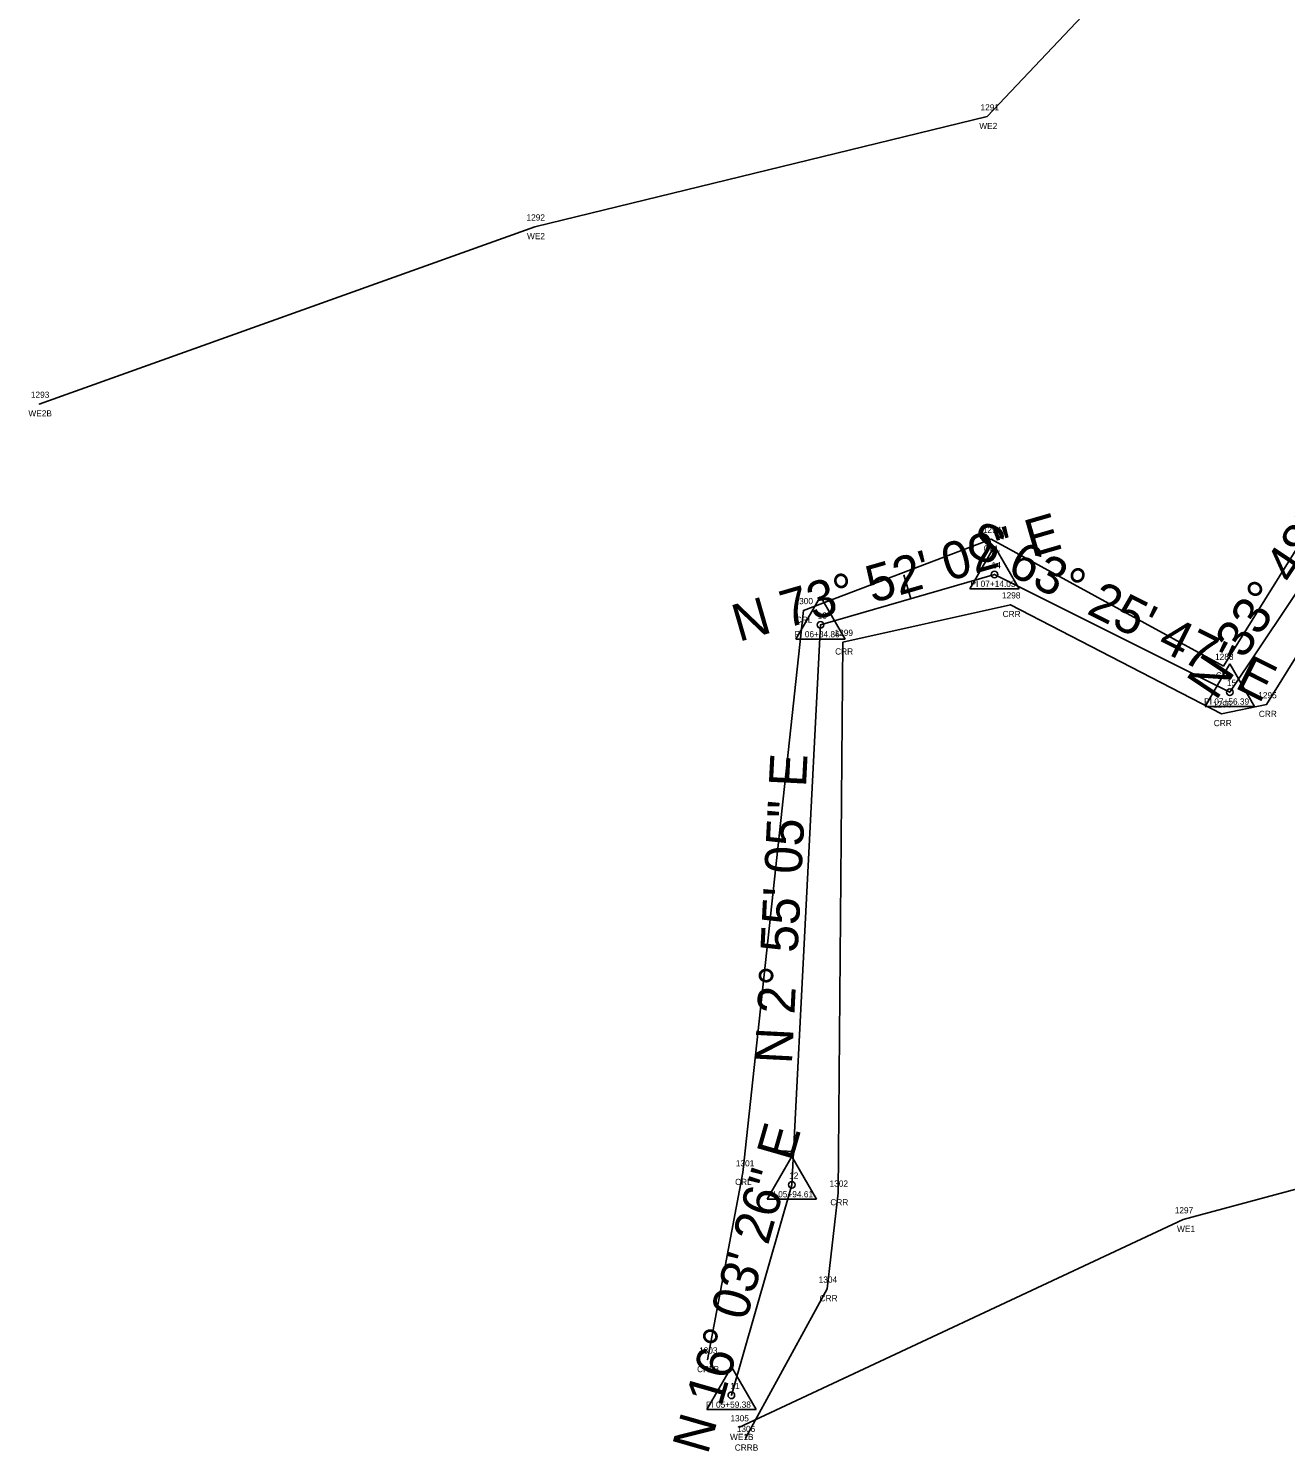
# Model space of a CAD drawing. Extents: x 2445178 to 2446205, y 790762 to 792372.
# Drawn here: x 2445177.9 to 2445380.3, y 791555 to 791784 of the extents above; entities that cross this region are included whole.
import ezdxf

# ---------------------------------------------------------------- set-up
doc = ezdxf.new("R2010")
doc.units = 0
for name, color, linetype in [('RD_EX_H2O', 7, 'Continuous'), ('RD_EX_H2O_txCode', 7, 'Continuous'), ('RD_HC_Cl', 7, 'Continuous'), ('RD_HC_Data', 7, 'Continuous'), ('RD_HC_Data_Tic', 7, 'Continuous'), ('RD_HC_txCode', 7, 'Continuous'), ('RD_SMD_Locator', 7, 'Continuous')]:
    doc.layers.add(name, color=color, linetype=linetype)

msp = doc.modelspace()

# ---------------------------------------------------------------- linework, layer by layer
at = {"layer": 'RD_EX_H2O'}
for points in [[(2445390.88, 791910.3), (2445382.88, 791823.37), (2445332.21, 791769.8), (2445259.4, 791752.08), (2445179.59, 791723.55)], [(2445748.32, 791780.49), (2445701.12, 791774.43), (2445677.09, 791767.59), (2445662.39, 791761.56), (2445644.36, 791766.93), (2445623.55, 791762.71), (2445618.49, 791746.46), (2445607.67, 791748.78), (2445606.64, 791748.27), (2445612.18, 791734.98), (2445561.56, 791692.97), (2445554.1, 791670.89), (2445517.8, 791656.91), (2445473.7, 791621.85), (2445363.77, 791592.3), (2445292.26, 791558.82)], [(2445601.06, 791763.87), (2445588.04, 791754.39), (2445544.11, 791733.92), (2445501.1, 791687.67), (2445464.95, 791685.09), (2445422.11, 791733.61), (2445413.32, 791729.6), (2445404.23, 791718.68), (2445377.21, 791675.18), (2445369.95, 791673.71), (2445335.95, 791691.26), (2445308.99, 791685.23), (2445308.22, 791596.59), (2445306.48, 791581.14), (2445293.31, 791557.11)], [(2445530.12, 791747.41), (2445491.74, 791707.13), (2445470.74, 791700.73), (2445420.06, 791750.24), (2445407.82, 791740.44), (2445395.12, 791721.24), (2445370.26, 791681.38), (2445332.86, 791701.82), (2445302.63, 791690.34), (2445292.86, 791599.86), (2445287.21, 791569.74)]]:
    msp.add_lwpolyline(points, dxfattribs=at)
at = {"layer": 'RD_HC_Cl'}
for p, q in [((2445371.27, 791677.17), (2445399.65, 791719.55)), ((2445305.37, 791688.01), (2445333.39, 791696.12)), ((2445333.39, 791696.12), (2445371.27, 791677.17)), ((2445300.78, 791597.88), (2445305.37, 791688.01)), ((2445291.03, 791564.02), (2445300.78, 791597.88))]:
    msp.add_line(p, q, dxfattribs=at)
at = {"layer": 'RD_HC_Data'}
for p, q in [((2445329.42, 791693.82), (2445333.39, 791700.7)), ((2445333.39, 791700.7), (2445337.36, 791693.82)), ((2445329.42, 791693.82), (2445337.36, 791693.82)), ((2445301.4, 791685.72), (2445305.37, 791692.6)), ((2445305.37, 791692.6), (2445309.34, 791685.72)), ((2445301.4, 791685.72), (2445309.34, 791685.72)), ((2445367.3, 791674.88), (2445371.27, 791681.76)), ((2445371.27, 791681.76), (2445375.24, 791674.88)), ((2445367.3, 791674.88), (2445375.24, 791674.88)), ((2445296.81, 791595.58), (2445300.78, 791602.46)), ((2445300.78, 791602.46), (2445304.75, 791595.58)), ((2445296.81, 791595.58), (2445304.75, 791595.58)), ((2445287.06, 791561.73), (2445291.04, 791568.61)), ((2445291.04, 791568.61), (2445295, 791561.73)), ((2445287.06, 791561.73), (2445295, 791561.73))]:
    msp.add_line(p, q, dxfattribs=at)
for centre in [(2445333.39, 791696.12), (2445305.37, 791688.01), (2445371.27, 791677.17), (2445300.78, 791597.88), (2445291.03, 791564.02)]:
    msp.add_circle(centre, 0.529, dxfattribs=at)
at = {"layer": 'RD_HC_Data_Tic'}
for p, q in [((2445319.91, 791692.22), (2445318.8, 791696.06)), ((2445301.05, 791603.26), (2445297.06, 791603.46))]:
    msp.add_line(p, q, dxfattribs=at)
at = {"layer": 'RD_SMD_Locator'}
for centre in [(2445332.21, 791769.8), (2445259.4, 791752.08), (2445179.59, 791723.55), (2445332.86, 791701.82), (2445333.39, 791696.12), (2445335.95, 791691.26), (2445302.63, 791690.34), (2445305.37, 791688.01), (2445308.99, 791685.23), (2445370.26, 791681.38), (2445371.27, 791677.17), (2445377.21, 791675.18), (2445369.95, 791673.71), (2445292.86, 791599.86), (2445300.78, 791597.88), (2445308.22, 791596.59), (2445363.77, 791592.3), (2445306.48, 791581.14), (2445287.21, 791569.74), (2445291.03, 791564.02), (2445292.26, 791558.82), (2445293.31, 791557.11)]:
    msp.add_circle(centre, 0.001, dxfattribs=at)

# ---------------------------------------------------------------- texts
at = {"layer": 'RD_EX_H2O_txCode'}
for s, p in [('1291', (2445331.15, 791770.8)), ('WE2', (2445330.95, 791767.8)), ('1292', (2445258.05, 791753.08)), ('WE2', (2445258.13, 791750.08)), ('1293', (2445178.25, 791724.55)), ('WE2B', (2445177.85, 791721.55)), ('1294', (2445331.51, 791702.82)), ('CRL', (2445331.63, 791699.82)), ('1298', (2445334.6, 791692.26)), ('1300', (2445301.2, 791691.34)), ('CRL', (2445301.4, 791688.34)), ('CRR', (2445334.7, 791689.26)), ('1299', (2445307.64, 791686.23)), ('CRR', (2445307.74, 791683.23)), ('1288', (2445368.91, 791682.38)), ('CRL', (2445369.03, 791679.38)), ('1295', (2445375.86, 791676.18)), ('1296', (2445368.58, 791674.71)), ('CRR', (2445368.7, 791671.71)), ('CRR', (2445375.96, 791673.18)), ('1301', (2445291.75, 791600.86)), ('CRL', (2445291.63, 791597.86)), ('1302', (2445306.84, 791597.59)), ('CRR', (2445306.97, 791594.59)), ('1297', (2445362.42, 791593.3)), ('WE1', (2445362.79, 791590.3)), ('1304', (2445305.09, 791582.14)), ('CRR', (2445305.23, 791579.14)), ('1303', (2445285.83, 791570.74)), ('CRLB', (2445285.51, 791567.74)), ('1305', (2445290.88, 791559.82)), ('1306', (2445291.9, 791558.11)), ('WE1B', (2445290.81, 791556.82)), ('CRRB', (2445291.58, 791555.11))]:
    msp.add_text(s, height=1, dxfattribs=at).set_placement(p)
at = {"layer": 'RD_HC_Data'}
for s, rotation, p in [('N 33%%d 48\' 23" E', 56.1936, (2445369.06, 791675.67)), ('N 73%%d 52\' 02" E', 16.1328, (2445292.23, 791685.25)), ('S 63%%d 25\' 47" E', 333.4297, (2445328.41, 791699.72)), ('N 2%%d 55\' 05" E', 87.0819, (2445300.77, 791617.25)), ('N 16%%d 03\' 26" E', 73.9428, (2445287.21, 791554.34))]:
    msp.add_text(s, height=6, rotation=rotation, dxfattribs=at).set_placement(p)
at = {"layer": 'RD_HC_txCode'}
for s, p in [('14', (2445332.94, 791697.12)), ('PI 07+14.03', (2445329.53, 791694.12)), ('13', (2445304.92, 791689.01)), ('PI 06+84.86', (2445301.22, 791686.01)), ('15', (2445370.82, 791678.17)), ('PI 07+56.39', (2445367.15, 791675.17)), ('12', (2445300.33, 791598.88)), ('PI 05+94.61', (2445296.94, 791595.88)), ('11', (2445290.87, 791565.02)), ('PI 05+59.38', (2445286.93, 791562.02))]:
    msp.add_text(s, height=1, dxfattribs=at).set_placement(p)

doc.saveas('drawing.dxf')
